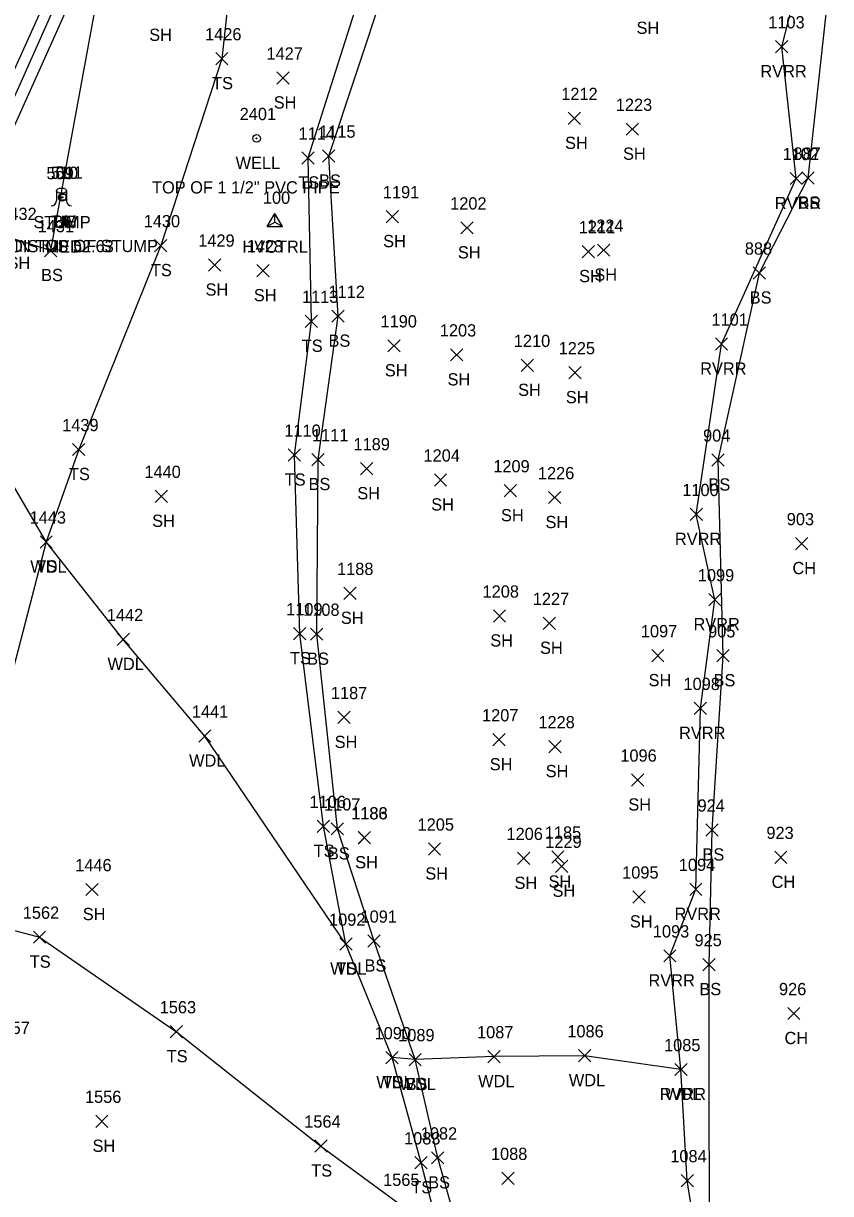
# Model space of a CAD drawing. Extents: x 1885914 to 1887218, y 756253 to 760620.
# Drawn here: x 1886519.5 to 1886651.6, y 759763.2 to 759954.5 of the extents above; entities that cross this region are included whole.
import ezdxf

# ---------------------------------------------------------------- set-up
doc = ezdxf.new("R2010")
doc.units = 0
for name, color, linetype in [('C_A', 7, 'Continuous'), ('C_C', 7, 'Continuous'), ('C_I', 7, 'Continuous'), ('CBP', 7, 'Continuous'), ('CPBM', 7, 'Continuous'), ('CPSM', 7, 'Continuous'), ('L_A', 7, 'Continuous'), ('L_C', 7, 'Continuous'), ('L_I', 7, 'Continuous'), ('L_TIC', 7, 'Continuous'), ('LAWA', 7, 'Continuous'), ('LAWE', 7, 'Continuous'), ('LELB', 7, 'Continuous'), ('LTS', 7, 'Continuous'), ('PET', 7, 'Continuous'), ('U_A', 7, 'Continuous'), ('U_C', 7, 'Continuous'), ('U_I', 7, 'Continuous'), ('UWW', 7, 'Continuous')]:
    doc.layers.add(name, color=color, linetype=linetype)

msp = doc.modelspace()

# ---------------------------------------------------------------- linework, layer by layer
at = {"layer": 'CBP'}
for radius in [0.625, 0.0833]:
    msp.add_circle((1886525.91, 759926.06), radius, dxfattribs=at)
at = {"layer": 'CPBM'}
for p, q in [((1886525.5, 759925.58), (1886525.5, 759926.58)), ((1886525.5, 759926.58), (1886526.5, 759926.58)), ((1886526, 759926.09), (1886526, 759926.09)), ((1886526, 759926.09), (1886526, 759926.09)), ((1886526.5, 759926.58), (1886526.5, 759925.58)), ((1886526.5, 759925.58), (1886525.5, 759925.58))]:
    msp.add_line(p, q, dxfattribs=at)
at = {"layer": 'CPSM'}
for p, q in [((1886559.42, 759921.26), (1886560.67, 759923.42)), ((1886559.42, 759921.26), (1886560.67, 759923.42)), ((1886559.42, 759921.26), (1886560.67, 759921.98)), ((1886559.42, 759921.26), (1886560.67, 759921.98)), ((1886561.92, 759921.26), (1886560.67, 759923.42)), ((1886560.67, 759921.98), (1886560.67, 759923.42)), ((1886561.92, 759921.26), (1886560.67, 759923.42)), ((1886560.67, 759921.98), (1886560.67, 759923.42)), ((1886560.67, 759921.98), (1886560.67, 759921.98)), ((1886560.67, 759921.98), (1886561.92, 759921.26)), ((1886560.67, 759921.98), (1886560.67, 759921.98)), ((1886560.67, 759921.98), (1886561.92, 759921.26)), ((1886559.42, 759921.26), (1886561.92, 759921.26)), ((1886559.42, 759921.26), (1886561.92, 759921.26))]:
    msp.add_line(p, q, dxfattribs=at)
at = {"layer": 'L_TIC'}
for points in [[(1886642.57, 759949.66), (1886644.57, 759951.66)], [(1886644.57, 759949.66), (1886642.57, 759951.66)], [(1886550.99, 759947.71), (1886552.99, 759949.71)], [(1886552.99, 759947.71), (1886550.99, 759949.71)], [(1886560.99, 759944.56), (1886562.99, 759946.56)], [(1886562.99, 759944.56), (1886560.99, 759946.56)], [(1886608.64, 759937.95), (1886610.64, 759939.95)], [(1886610.64, 759937.95), (1886608.64, 759939.95)], [(1886618.13, 759936.18), (1886620.13, 759938.18)], [(1886620.13, 759936.18), (1886618.13, 759938.18)], [(1886565.1, 759931.48), (1886567.1, 759933.48)], [(1886567.1, 759931.48), (1886565.1, 759933.48)], [(1886568.47, 759931.79), (1886570.47, 759933.79)], [(1886570.47, 759931.79), (1886568.47, 759933.79)], [(1886644.92, 759928.12), (1886646.92, 759930.12)], [(1886646.92, 759928.12), (1886644.92, 759930.12)], [(1886646.85, 759928.2), (1886648.85, 759930.2)], [(1886648.85, 759928.2), (1886646.85, 759930.2)], [(1886578.89, 759921.89), (1886580.89, 759923.89)], [(1886580.89, 759921.89), (1886578.89, 759923.89)], [(1886591.11, 759920.05), (1886593.11, 759922.05)], [(1886593.11, 759920.05), (1886591.11, 759922.05)], [(1886523, 759916.34), (1886525, 759918.34)], [(1886525, 759916.34), (1886523, 759918.34)], [(1886541, 759917.15), (1886543, 759919.15)], [(1886543, 759917.15), (1886541, 759919.15)], [(1886610.94, 759916.17), (1886612.94, 759918.17)], [(1886612.94, 759916.17), (1886610.94, 759918.17)], [(1886613.43, 759916.41), (1886615.43, 759918.41)], [(1886615.43, 759916.41), (1886613.43, 759918.41)], [(1886549.84, 759913.97), (1886551.84, 759915.97)], [(1886551.84, 759913.97), (1886549.84, 759915.97)], [(1886557.74, 759913.05), (1886559.74, 759915.05)], [(1886559.74, 759913.05), (1886557.74, 759915.05)], [(1886638.89, 759912.67), (1886640.89, 759914.67)], [(1886640.89, 759912.67), (1886638.89, 759914.67)], [(1886565.65, 759904.78), (1886567.65, 759906.78)], [(1886567.65, 759904.78), (1886565.65, 759906.78)], [(1886570, 759905.61), (1886572, 759907.61)], [(1886572, 759905.61), (1886570, 759907.61)], [(1886579.16, 759900.77), (1886581.16, 759902.77)], [(1886581.16, 759900.77), (1886579.16, 759902.77)], [(1886632.72, 759901.05), (1886634.72, 759903.05)], [(1886634.72, 759901.05), (1886632.72, 759903.05)], [(1886589.42, 759899.29), (1886591.42, 759901.29)], [(1886591.42, 759899.29), (1886589.42, 759901.29)], [(1886600.96, 759897.57), (1886602.96, 759899.57)], [(1886602.96, 759897.57), (1886600.96, 759899.57)], [(1886608.77, 759896.38), (1886610.77, 759898.38)], [(1886610.77, 759896.38), (1886608.77, 759898.38)], [(1886527.59, 759883.81), (1886529.59, 759885.81)], [(1886529.59, 759883.81), (1886527.59, 759885.81)], [(1886562.87, 759882.9), (1886564.87, 759884.9)], [(1886564.87, 759882.9), (1886562.87, 759884.9)], [(1886566.73, 759882.17), (1886568.73, 759884.17)], [(1886568.73, 759882.17), (1886566.73, 759884.17)], [(1886632.14, 759882.1), (1886634.14, 759884.1)], [(1886634.14, 759882.1), (1886632.14, 759884.1)], [(1886574.67, 759880.68), (1886576.67, 759882.68)], [(1886576.67, 759880.68), (1886574.67, 759882.68)], [(1886586.75, 759878.84), (1886588.75, 759880.84)], [(1886588.75, 759878.84), (1886586.75, 759880.84)], [(1886541.11, 759876.16), (1886543.11, 759878.16)], [(1886543.11, 759876.16), (1886541.11, 759878.16)], [(1886598.17, 759877.08), (1886600.17, 759879.08)], [(1886600.17, 759877.08), (1886598.17, 759879.08)], [(1886605.44, 759875.96), (1886607.44, 759877.96)], [(1886607.44, 759875.96), (1886605.44, 759877.96)], [(1886628.59, 759873.2), (1886630.59, 759875.2)], [(1886630.59, 759873.2), (1886628.59, 759875.2)], [(1886522.26, 759868.7), (1886524.26, 759870.7)], [(1886524.26, 759868.7), (1886522.26, 759870.7)], [(1886522.26, 759868.7), (1886524.26, 759870.7)], [(1886524.26, 759868.7), (1886522.26, 759870.7)], [(1886645.83, 759868.43), (1886647.83, 759870.43)], [(1886647.83, 759868.43), (1886645.83, 759870.43)], [(1886571.97, 759860.3), (1886573.97, 759862.3)], [(1886573.97, 759860.3), (1886571.97, 759862.3)], [(1886631.62, 759859.26), (1886633.62, 759861.26)], [(1886633.62, 759859.26), (1886631.62, 759861.26)], [(1886596.41, 759856.6), (1886598.41, 759858.6)], [(1886598.41, 759856.6), (1886596.41, 759858.6)], [(1886604.54, 759855.4), (1886606.54, 759857.4)], [(1886606.54, 759855.4), (1886604.54, 759857.4)], [(1886563.73, 759853.7), (1886565.73, 759855.7)], [(1886565.73, 759853.7), (1886563.73, 759855.7)], [(1886566.51, 759853.62), (1886568.51, 759855.62)], [(1886568.51, 759853.62), (1886566.51, 759855.62)], [(1886534.88, 759852.76), (1886536.88, 759854.76)], [(1886536.88, 759852.76), (1886534.88, 759854.76)], [(1886622.3, 759850.11), (1886624.3, 759852.11)], [(1886624.3, 759850.11), (1886622.3, 759852.11)], [(1886632.96, 759850.09), (1886634.96, 759852.09)], [(1886634.96, 759850.09), (1886632.96, 759852.09)], [(1886629.27, 759841.49), (1886631.27, 759843.49)], [(1886631.27, 759841.49), (1886629.27, 759843.49)], [(1886570.96, 759840.01), (1886572.96, 759842.01)], [(1886572.96, 759840.01), (1886570.96, 759842.01)], [(1886548.22, 759836.96), (1886550.22, 759838.96)], [(1886550.22, 759836.96), (1886548.22, 759838.96)], [(1886596.33, 759836.36), (1886598.33, 759838.36)], [(1886598.33, 759836.36), (1886596.33, 759838.36)], [(1886605.47, 759835.24), (1886607.47, 759837.24)], [(1886607.47, 759835.24), (1886605.47, 759837.24)], [(1886619, 759829.78), (1886621, 759831.78)], [(1886621, 759829.78), (1886619, 759831.78)], [(1886567.6, 759822.21), (1886569.6, 759824.21)], [(1886569.6, 759822.21), (1886567.6, 759824.21)], [(1886569.9, 759821.79), (1886571.9, 759823.79)], [(1886571.9, 759821.79), (1886569.9, 759823.79)], [(1886574.31, 759820.34), (1886576.31, 759822.34)], [(1886576.31, 759820.34), (1886574.31, 759822.34)], [(1886574.33, 759820.34), (1886576.33, 759822.34)], [(1886576.33, 759820.34), (1886574.33, 759822.34)], [(1886631.16, 759821.61), (1886633.16, 759823.61)], [(1886633.16, 759821.61), (1886631.16, 759823.61)], [(1886585.78, 759818.5), (1886587.78, 759820.5)], [(1886587.78, 759818.5), (1886585.78, 759820.5)], [(1886600.37, 759816.97), (1886602.37, 759818.97)], [(1886602.37, 759816.97), (1886600.37, 759818.97)], [(1886605.95, 759817.19), (1886607.95, 759819.19)], [(1886607.95, 759817.19), (1886605.95, 759819.19)], [(1886642.42, 759817.14), (1886644.42, 759819.14)], [(1886644.42, 759817.14), (1886642.42, 759819.14)], [(1886606.59, 759815.68), (1886608.59, 759817.68)], [(1886608.59, 759815.68), (1886606.59, 759817.68)], [(1886529.77, 759811.87), (1886531.77, 759813.87)], [(1886531.77, 759811.87), (1886529.77, 759813.87)], [(1886628.52, 759811.91), (1886630.52, 759813.91)], [(1886630.52, 759811.91), (1886628.52, 759813.91)], [(1886619.24, 759810.66), (1886621.24, 759812.66)], [(1886621.24, 759810.66), (1886619.24, 759812.66)], [(1886521.18, 759804.09), (1886523.18, 759806.09)], [(1886523.18, 759804.09), (1886521.18, 759806.09)], [(1886575.89, 759803.45), (1886577.89, 759805.45)], [(1886577.89, 759803.45), (1886575.89, 759805.45)], [(1886571.3, 759802.95), (1886573.3, 759804.95)], [(1886573.3, 759802.95), (1886571.3, 759804.95)], [(1886571.3, 759802.95), (1886573.3, 759804.95)], [(1886573.3, 759802.95), (1886571.3, 759804.95)], [(1886624.27, 759801.03), (1886626.27, 759803.03)], [(1886626.27, 759801.03), (1886624.27, 759803.03)], [(1886630.66, 759799.6), (1886632.66, 759801.6)], [(1886632.66, 759799.6), (1886630.66, 759801.6)], [(1886644.54, 759791.6), (1886646.54, 759793.6)], [(1886646.54, 759791.6), (1886644.54, 759793.6)], [(1886543.57, 759788.63), (1886545.57, 759790.63)], [(1886545.57, 759788.63), (1886543.57, 759790.63)], [(1886578.84, 759784.39), (1886580.84, 759786.39)], [(1886580.84, 759784.39), (1886578.84, 759786.39)], [(1886578.84, 759784.39), (1886580.84, 759786.39)], [(1886580.84, 759784.39), (1886578.84, 759786.39)], [(1886582.62, 759784.07), (1886584.62, 759786.07)], [(1886584.62, 759784.07), (1886582.62, 759786.07)], [(1886582.62, 759784.07), (1886584.62, 759786.07)], [(1886584.62, 759784.07), (1886582.62, 759786.07)], [(1886595.5, 759784.55), (1886597.5, 759786.55)], [(1886597.5, 759784.55), (1886595.5, 759786.55)], [(1886610.33, 759784.7), (1886612.33, 759786.7)], [(1886612.33, 759784.7), (1886610.33, 759786.7)], [(1886626.09, 759782.44), (1886628.09, 759784.44)], [(1886628.09, 759782.44), (1886626.09, 759784.44)], [(1886626.09, 759782.44), (1886628.09, 759784.44)], [(1886628.09, 759782.44), (1886626.09, 759784.44)], [(1886531.36, 759773.98), (1886533.36, 759775.98)], [(1886533.36, 759773.98), (1886531.36, 759775.98)], [(1886567.21, 759769.94), (1886569.21, 759771.94)], [(1886569.21, 759769.94), (1886567.21, 759771.94)], [(1886583.57, 759767.2), (1886585.57, 759769.2)], [(1886585.57, 759767.2), (1886583.57, 759769.2)], [(1886586.3, 759768), (1886588.3, 759770)], [(1886588.3, 759768), (1886586.3, 759770)], [(1886597.78, 759764.66), (1886599.78, 759766.66)], [(1886599.78, 759764.66), (1886597.78, 759766.66)], [(1886627.11, 759764.28), (1886629.11, 759766.28)], [(1886629.11, 759764.28), (1886627.11, 759766.28)]]:
    msp.add_lwpolyline(points, dxfattribs=at)
at = {"layer": 'LAWA'}
msp.add_lwpolyline([(1886627.09, 759783.44), (1886611.33, 759785.7), (1886596.5, 759785.55), (1886583.62, 759785.07), (1886579.84, 759785.39), (1886572.3, 759803.95), (1886549.22, 759837.96), (1886535.88, 759853.76), (1886523.26, 759869.7), (1886507.15, 759897.34)], dxfattribs=at)
at = {"layer": 'LAWE'}
msp.add_lwpolyline([(1886640.49, 759642.77), (1886639.36, 759650.41), (1886638.96, 759653.9), (1886632.66, 759676.07), (1886629.25, 759698.11), (1886627.43, 759722.42), (1886630.5, 759750.23), (1886628.11, 759765.28), (1886627.09, 759783.44), (1886625.27, 759802.03), (1886629.52, 759812.91), (1886630.27, 759842.49), (1886632.62, 759860.26), (1886629.59, 759874.2), (1886633.72, 759902.05), (1886645.92, 759929.12), (1886643.57, 759950.66), (1886647.93, 759967.68)], dxfattribs=at)
at = {"layer": 'LELB'}
for points in [[(1886725.27, 760338.09), (1886712.33, 760310.28), (1886698.46, 760286.41), (1886683.25, 760252.31), (1886665.56, 760220.6), (1886649.26, 760186.3), (1886631.93, 760155.48), (1886614.95, 760123.77), (1886599.48, 760094.94), (1886586.46, 760070.53), (1886572.04, 760041.07), (1886559.72, 760022.59), (1886545.87, 759996.97), (1886529.41, 759963.14), (1886510.6, 759921.25), (1886501.24, 759900.36), (1886492.69, 759872.91), (1886485.39, 759846.95), (1886480.56, 759824.59), (1886476.3, 759808.27), (1886477.13, 759795.21)], [(1886572.3, 759803.95), (1886568.6, 759823.21), (1886564.73, 759854.7), (1886563.87, 759883.9), (1886566.65, 759905.78), (1886566.1, 759932.48), (1886575.22, 759961.15), (1886584.71, 759987.76), (1886595.18, 760013.31), (1886601.19, 760034.22), (1886605.14, 760059.41), (1886622.97, 760086.15), (1886635.93, 760094.98), (1886646.75, 760112.81), (1886658.85, 760130.9), (1886680.3, 760148.52), (1886699.66, 760159.95), (1886715.31, 760165.82), (1886739.18, 760176.38)], [(1886564.69, 760023.37), (1886556.81, 759992.84), (1886551.99, 759948.71), (1886542, 759918.15), (1886528.59, 759884.81), (1886523.26, 759869.7), (1886515.99, 759841.78), (1886514.24, 759821.96)], [(1886559.72, 760022.59), (1886549.4, 759996.33), (1886532.08, 759961.59), (1886524, 759917.34), (1886512.94, 759920.8), (1886504.17, 759899.59), (1886494.61, 759872.13), (1886487.33, 759846.58), (1886481.7, 759824.1), (1886477.83, 759807.91), (1886479.96, 759798.66)], [(1886527.64, 759964.02), (1886508.85, 759921.99), (1886500.17, 759900.4), (1886490.04, 759873.78), (1886482, 759847.55), (1886476.31, 759825.69), (1886474.25, 759817.99), (1886471.86, 759803.75), (1886464.28, 759781.47), (1886459.74, 759761.62), (1886455.11, 759738.34), (1886453.91, 759709.07), (1886450.32, 759686.96), (1886450.55, 759665.25), (1886450.92, 759642.65), (1886453.45, 759622.64), (1886456.79, 759611.09)], [(1886651.59, 759963.58), (1886647.85, 759929.2), (1886639.89, 759913.67), (1886633.14, 759883.1), (1886633.96, 759851.09), (1886632.16, 759822.61), (1886631.66, 759800.6), (1886631.69, 759739.71), (1886631.53, 759709.44), (1886635.98, 759687.07), (1886641.47, 759657.6), (1886645.02, 759644.27), (1886643.52, 759637.8), (1886640.86, 759635.28), (1886641.28, 759631.71), (1886642.18, 759628.94), (1886648.32, 759617.92), (1886654.14, 759597.23), (1886659.93, 759557.18), (1886668.26, 759522.06), (1886683.34, 759437.14), (1886685.68, 759384.91)], [(1886617.45, 759694.6), (1886609.12, 759710.92), (1886596.7, 759735.77), (1886587.3, 759769), (1886583.62, 759785.07), (1886576.89, 759804.45), (1886570.9, 759822.79), (1886567.51, 759854.62), (1886567.73, 759883.17), (1886571, 759906.61), (1886569.47, 759932.79), (1886578.55, 759960.06)], [(1886491.13, 759804.2), (1886501.13, 759810.72), (1886522.18, 759805.09), (1886544.57, 759789.63), (1886568.21, 759770.94), (1886581.11, 759761.41), (1886584.27, 759751.77)], [(1886638.96, 759653.9), (1886625.7, 759678.66), (1886616.18, 759693.78), (1886606.91, 759709.6), (1886593.74, 759732.8), (1886584.57, 759768.2), (1886579.84, 759785.39)]]:
    msp.add_lwpolyline(points, dxfattribs=at)
at = {"layer": 'LTS'}
for p, q in [((1886524.93, 759927.13), (1886524.93, 759925.47)), ((1886525.76, 759925.99), (1886525.76, 759925.99)), ((1886525.76, 759925.99), (1886525.76, 759925.99)), ((1886525.76, 759925.97), (1886525.76, 759925.97)), ((1886526.6, 759926.97), (1886526.6, 759927.13)), ((1886526.6, 759927.13), (1886526.6, 759925.47))]:
    msp.add_line(p, q, dxfattribs=at)
msp.add_circle((1886525.76, 759925.99), 0.0833, dxfattribs=at)
for centre, start, end in [((1886524.1, 759925.47), 270, 360), ((1886527.43, 759925.47), 180, 270)]:
    msp.add_arc(centre, 0.833, start, end, dxfattribs=at)
msp.add_ellipse((1886525.76, 759927.13), major_axis=(-0.833, 0), ratio=0.5, dxfattribs=at)
at = {"layer": 'PET'}
msp.add_lwpolyline([(1886526.14, 759964.92), (1886507.07, 759922.75), (1886498.17, 759900.86), (1886488.16, 759874.15), (1886479.62, 759848.04), (1886473, 759827.05), (1886466.37, 759803.11), (1886458.99, 759773.42), (1886453.36, 759746.97), (1886448.76, 759720.11), (1886445.71, 759693.61), (1886444.44, 759668.96), (1886443.78, 759643.55), (1886445.31, 759617.59), (1886448.26, 759589.04), (1886453.63, 759558.69), (1886458.27, 759533.55), (1886466.8, 759496), (1886474.35, 759464.49), (1886481.64, 759434.54), (1886491.18, 759398.8), (1886502.68, 759358.39), (1886508.23, 759337.95)], dxfattribs=at)
at = {"layer": 'UWW'}
for radius in [0.625, 0.0833]:
    msp.add_circle((1886557.68, 759935.67), radius, dxfattribs=at)

# ---------------------------------------------------------------- texts
at = {"layer": 'C_A'}
for s, p in [('TIE', (1886523.99, 759921.06)), ('BM', (1886524.31, 759921.09)), ('HVCTRL', (1886555.37, 759916.98)), ('HVCTRL', (1886555.37, 759916.98))]:
    msp.add_text(s, height=2, dxfattribs=at).set_placement(p)
at = {"layer": 'C_C'}
for s, p in [('RR SPIKE IN TOP OF STUMP', (1886504.84, 759917.09)), ('TIE DIST IS 52.63', (1886512.62, 759917.06))]:
    msp.add_text(s, height=2, dxfattribs=at).set_placement(p)
at = {"layer": 'C_I'}
for s, p in [('510', (1886524.03, 759929.06)), ('511', (1886524.77, 759929.09)), ('100', (1886558.71, 759924.98)), ('100', (1886558.71, 759924.98))]:
    msp.add_text(s, height=2, dxfattribs=at).set_placement(p)
at = {"layer": 'L_A'}
for s, p in [('SH', (1886619.81, 759952.76)), ('SH', (1886540.12, 759951.62)), ('RVRR', (1886640.08, 759945.66)), ('TS', (1886550.4, 759943.71)), ('SH', (1886560.48, 759940.56)), ('SH', (1886608.13, 759933.95)), ('SH', (1886617.61, 759932.18)), ('TS', (1886564.51, 759927.48)), ('BS', (1886567.91, 759927.79)), ('RVRR', (1886642.43, 759924.12)), ('BS', (1886646.29, 759924.2)), ('STUMP', (1886521.18, 759920.99)), ('SH', (1886578.38, 759917.89)), ('SH', (1886590.6, 759916.05)), ('SH', (1886516.94, 759914.34)), ('BS', (1886522.44, 759912.34)), ('TS', (1886540.4, 759913.15)), ('SH', (1886610.43, 759912.17)), ('SH', (1886612.92, 759912.41)), ('SH', (1886549.33, 759909.97)), ('SH', (1886557.23, 759909.05)), ('BS', (1886638.33, 759908.67)), ('TS', (1886565.06, 759900.78)), ('BS', (1886569.44, 759901.61)), ('RVRR', (1886630.23, 759897.05)), ('SH', (1886578.65, 759896.77)), ('SH', (1886588.91, 759895.29)), ('SH', (1886600.45, 759893.57)), ('SH', (1886608.26, 759892.38)), ('TS', (1886527, 759879.81)), ('TS', (1886562.28, 759878.9)), ('BS', (1886566.17, 759878.17)), ('BS', (1886631.58, 759878.1)), ('SH', (1886574.15, 759876.68)), ('SH', (1886586.24, 759874.84)), ('SH', (1886540.6, 759872.16)), ('SH', (1886597.65, 759873.08)), ('SH', (1886604.93, 759871.96)), ('RVRR', (1886626.1, 759869.2)), ('WDL', (1886520.67, 759864.7)), ('TS', (1886521.67, 759864.7)), ('CH', (1886645.32, 759864.43)), ('SH', (1886571.46, 759856.3)), ('RVRR', (1886629.14, 759855.26)), ('SH', (1886595.9, 759852.6)), ('SH', (1886604.03, 759851.4)), ('TS', (1886563.14, 759849.7)), ('BS', (1886565.95, 759849.62)), ('WDL', (1886533.3, 759848.76)), ('SH', (1886621.79, 759846.11)), ('BS', (1886632.41, 759846.09)), ('SH', (1886570.45, 759836.01)), ('RVRR', (1886626.78, 759837.49)), ('WDL', (1886546.64, 759832.96)), ('SH', (1886595.81, 759832.36)), ('SH', (1886604.96, 759831.24)), ('SH', (1886618.48, 759825.78)), ('TS', (1886567.01, 759818.21)), ('BS', (1886569.34, 759817.79)), ('BS', (1886630.6, 759817.61)), ('SH', (1886573.79, 759816.34)), ('SH', (1886573.81, 759816.34)), ('SH', (1886585.27, 759814.5)), ('SH', (1886599.86, 759812.97)), ('SH', (1886605.43, 759813.19)), ('CH', (1886641.91, 759813.14)), ('SH', (1886606.08, 759811.68)), ('SH', (1886529.25, 759807.87)), ('RVRR', (1886626.03, 759807.91)), ('SH', (1886618.73, 759806.66)), ('TS', (1886520.58, 759800.09)), ('BS', (1886575.33, 759799.45)), ('WDL', (1886569.72, 759798.95)), ('TS', (1886570.71, 759798.95)), ('RVRR', (1886621.78, 759797.03)), ('BS', (1886630.1, 759795.6)), ('CH', (1886644.02, 759787.6)), ('TS', (1886542.98, 759784.63)), ('WDL', (1886577.26, 759780.39)), ('TS', (1886578.25, 759780.39)), ('WDL', (1886593.91, 759780.55)), ('WDL', (1886608.75, 759780.7)), ('WDL', (1886581.04, 759780.07)), ('BS', (1886582.06, 759780.07)), ('RVRR', (1886623.61, 759778.44)), ('WDL', (1886624.51, 759778.44)), ('SH', (1886530.85, 759769.98)), ('TS', (1886566.62, 759765.94)), ('TS', (1886582.98, 759763.2)), ('BS', (1886585.74, 759764))]:
    msp.add_text(s, height=2, dxfattribs=at).set_placement(p)
at = {"layer": 'L_C'}
msp.add_text('MED', height=2, dxfattribs=at).set_placement((1886523.17, 759916.99))
at = {"layer": 'L_I'}
for s, p in [('1103', (1886641.36, 759953.66)), ('1426', (1886549.25, 759951.71)), ('1427', (1886559.3, 759948.56)), ('1212', (1886607.51, 759941.95)), ('1223', (1886616.43, 759940.18)), ('1114', (1886564.54, 759935.48)), ('1115', (1886567.91, 759935.79)), ('1102', (1886643.71, 759932.12)), ('887', (1886645.48, 759932.2)), ('509', (1886523.31, 759928.99)), ('1191', (1886578.33, 759925.89)), ('1202', (1886589.34, 759924.05)), ('1432', (1886515.76, 759922.34)), ('1431', (1886521.87, 759920.34)), ('1430', (1886539.22, 759921.15)), ('1211', (1886610.38, 759920.17)), ('1224', (1886611.74, 759920.41)), ('1429', (1886548.14, 759917.97)), ('1428', (1886556.05, 759917.05)), ('888', (1886637.53, 759916.67)), ('1113', (1886565.1, 759908.78)), ('1112', (1886569.44, 759909.61)), ('1190', (1886577.95, 759904.77)), ('1101', (1886632.08, 759905.05)), ('1203', (1886587.65, 759903.29)), ('1210', (1886599.75, 759901.57)), ('1225', (1886607.08, 759900.38)), ('1439', (1886525.89, 759887.81)), ('1110', (1886562.22, 759886.9)), ('1111', (1886566.74, 759886.17)), ('904', (1886630.7, 759886.1)), ('1189', (1886573.53, 759884.68)), ('1204', (1886584.98, 759882.84)), ('1440', (1886539.33, 759880.16)), ('1209', (1886596.39, 759881.08)), ('1226', (1886603.69, 759879.96)), ('1100', (1886627.3, 759877.2)), ('1443', (1886520.56, 759872.7)), ('1443', (1886520.56, 759872.7)), ('903', (1886644.39, 759872.43)), ('1188', (1886570.84, 759864.3)), ('1099', (1886629.84, 759863.26)), ('1208', (1886594.64, 759860.6)), ('1227', (1886602.85, 759859.4)), ('1442', (1886533.19, 759856.76)), ('1109', (1886562.52, 759857.7)), ('1108', (1886565.3, 759857.62)), ('1097', (1886620.53, 759854.11)), ('905', (1886631.52, 759854.09)), ('1098', (1886627.5, 759845.49)), ('1187', (1886569.83, 759844.01)), ('1441', (1886547.1, 759840.96)), ('1207', (1886594.55, 759840.36)), ('1228', (1886603.77, 759839.24)), ('1096', (1886617.17, 759833.78)), ('1106', (1886566.34, 759826.21)), ('1107', (1886568.7, 759825.79)), ('1186', (1886573.14, 759824.34)), ('1183', (1886573.18, 759824.34)), ('924', (1886629.8, 759825.61)), ('1205', (1886584.01, 759822.5)), ('1206', (1886598.55, 759820.97)), ('1185', (1886604.82, 759821.19)), ('923', (1886641.06, 759821.14)), ('1229', (1886604.89, 759819.68)), ('1446', (1886528.02, 759815.87)), ('1095', (1886617.47, 759814.66)), ('1094', (1886626.74, 759815.91)), ('1562', (1886519.44, 759808.09)), ('1092', (1886569.53, 759806.95)), ('1092', (1886569.53, 759806.95)), ('1091', (1886574.68, 759807.45)), ('1093', (1886622.49, 759805.03)), ('925', (1886629.3, 759803.6)), ('926', (1886643.12, 759795.6)), ('1563', (1886541.83, 759792.63)), ('1557', (1886514.64, 759789.25)), ('1090', (1886576.98, 759788.39)), ('1090', (1886576.98, 759788.39)), ('1089', (1886580.84, 759788.07)), ('1089', (1886580.84, 759788.07)), ('1087', (1886593.73, 759788.55)), ('1086', (1886608.5, 759788.7)), ('1085', (1886624.32, 759786.44)), ('1085', (1886624.32, 759786.44)), ('1556', (1886529.61, 759777.98)), ('1564', (1886565.47, 759773.94)), ('1083', (1886581.8, 759771.2)), ('1082', (1886584.53, 759772)), ('1088', (1886596.01, 759768.66)), ('1084', (1886625.34, 759768.28)), ('1565', (1886578.37, 759764.41))]:
    msp.add_text(s, height=2, dxfattribs=at).set_placement(p)
at = {"layer": 'U_A'}
msp.add_text('WELL', height=2, dxfattribs=at).set_placement((1886554.25, 759930.67))
at = {"layer": 'U_C'}
msp.add_text('TOP OF 1 1/2" PVC PIPE', height=2, dxfattribs=at).set_placement((1886540.58, 759926.67))
at = {"layer": 'U_I'}
msp.add_text('2401', height=2, dxfattribs=at).set_placement((1886554.91, 759938.67))

doc.saveas('drawing.dxf')
